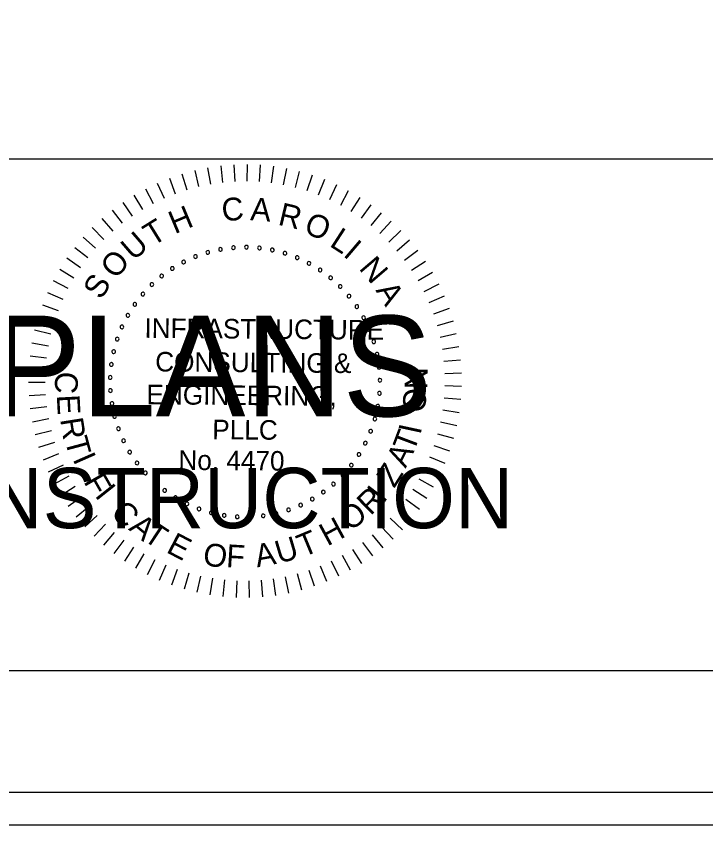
# Model space of a CAD drawing. Extents: x 967 to 1326, y 964 to 2584.
# Drawn here: x 1189.3 to 1212.88, y 2363.72 to 2391.36 of the extents above; entities that cross this region are included whole.
import ezdxf

# ---------------------------------------------------------------- set-up
doc = ezdxf.new("R2010")
doc.units = 0
for name, color, linetype in [('RD_SHT_Misc1', 7, 'Continuous'), ('RD_SHT_Misc2', 7, 'Continuous'), ('RD_XS_ExPaveRet', 7, 'Continuous'), ('RD_XS_TX_Elev_EX', 7, 'Continuous')]:
    doc.layers.add(name, color=color, linetype=linetype)

msp = doc.modelspace()

# ---------------------------------------------------------------- linework, layer by layer
at = {"layer": 'RD_SHT_Misc1'}
for p, q in [((1195.846, 2386.181), (1195.945, 2385.62)), ((1196.292, 2386.245), (1196.357, 2385.68)), ((1196.742, 2386.282), (1196.772, 2385.714)), ((1197.194, 2386.292), (1197.189, 2385.723)), ((1197.645, 2386.274), (1197.606, 2385.706)), ((1198.094, 2386.228), (1198.02, 2385.664)), ((1198.54, 2386.156), (1198.432, 2385.596)), ((1194.968, 2385.971), (1195.134, 2385.427)), ((1195.403, 2386.09), (1195.536, 2385.536)), ((1198.98, 2386.056), (1198.838, 2385.504)), ((1199.414, 2385.929), (1199.238, 2385.387)), ((1194.122, 2385.656), (1194.353, 2385.136)), ((1194.54, 2385.827), (1194.739, 2385.293)), ((1199.839, 2385.777), (1199.63, 2385.246)), ((1200.253, 2385.598), (1200.013, 2385.082)), ((1193.715, 2385.461), (1193.978, 2384.956)), ((1200.656, 2385.395), (1200.385, 2384.894)), ((1193.321, 2385.241), (1193.614, 2384.752)), ((1201.047, 2385.167), (1200.745, 2384.684)), ((1192.94, 2384.997), (1193.263, 2384.528)), ((1201.422, 2384.917), (1201.092, 2384.453)), ((1192.576, 2384.731), (1192.926, 2384.282)), ((1201.781, 2384.643), (1201.424, 2384.2)), ((1192.228, 2384.443), (1192.605, 2384.016)), ((1202.124, 2384.349), (1201.739, 2383.928)), ((1191.899, 2384.134), (1192.301, 2383.731)), ((1202.447, 2384.034), (1202.038, 2383.638)), ((1191.589, 2383.805), (1192.015, 2383.428)), ((1202.751, 2383.7), (1202.318, 2383.329)), ((1191.299, 2383.459), (1191.748, 2383.108)), ((1203.034, 2383.348), (1202.579, 2383.004)), ((1191.032, 2383.095), (1191.501, 2382.772)), ((1203.294, 2382.979), (1202.82, 2382.664)), ((1190.787, 2382.716), (1191.274, 2382.422)), ((1203.532, 2382.595), (1203.04, 2382.31)), ((1190.565, 2382.323), (1191.07, 2382.059)), ((1203.746, 2382.198), (1203.237, 2381.943)), ((1190.368, 2381.916), (1190.888, 2381.684)), ((1203.936, 2381.788), (1203.412, 2381.564)), ((1190.196, 2381.499), (1190.729, 2381.299)), ((1204.1, 2381.367), (1203.563, 2381.176)), ((1190.05, 2381.072), (1190.594, 2380.905)), ((1204.238, 2380.937), (1203.691, 2380.779)), ((1189.93, 2380.636), (1190.484, 2380.503)), ((1204.349, 2380.5), (1203.794, 2380.375)), ((1189.837, 2380.195), (1190.398, 2380.095)), ((1204.434, 2380.056), (1203.872, 2379.966)), ((1189.771, 2379.748), (1190.337, 2379.683)), ((1204.491, 2379.608), (1203.925, 2379.552)), ((1189.732, 2379.298), (1190.301, 2379.267)), ((1204.522, 2379.158), (1203.953, 2379.137)), ((1189.721, 2378.847), (1190.29, 2378.851)), ((1204.524, 2378.706), (1203.955, 2378.72)), ((1189.737, 2378.396), (1190.306, 2378.434)), ((1204.499, 2378.256), (1203.932, 2378.304)), ((1189.781, 2377.946), (1190.346, 2378.019)), ((1204.447, 2377.807), (1203.884, 2377.89)), ((1189.852, 2377.5), (1190.412, 2377.608)), ((1204.367, 2377.363), (1203.81, 2377.479)), ((1189.951, 2377.06), (1190.502, 2377.201)), ((1204.261, 2376.924), (1203.712, 2377.074)), ((1190.076, 2376.626), (1190.617, 2376.8)), ((1204.128, 2376.492), (1203.589, 2376.676)), ((1190.227, 2376.2), (1190.757, 2376.408)), ((1203.969, 2376.07), (1203.442, 2376.286)), ((1190.403, 2375.785), (1190.92, 2376.024)), ((1190.605, 2375.381), (1191.106, 2375.651)), ((1203.784, 2375.658), (1203.271, 2375.906)), ((1203.574, 2375.258), (1203.078, 2375.537)), ((1190.831, 2374.99), (1191.315, 2375.291)), ((1203.341, 2374.871), (1202.862, 2375.18)), ((1191.081, 2374.614), (1191.545, 2374.943)), ((1203.085, 2374.5), (1202.626, 2374.837)), ((1191.353, 2374.253), (1191.796, 2374.61)), ((1191.646, 2373.91), (1192.067, 2374.293)), ((1202.806, 2374.145), (1202.368, 2374.509)), ((1191.96, 2373.585), (1192.356, 2373.994)), ((1202.506, 2373.807), (1202.092, 2374.197)), ((1192.293, 2373.28), (1192.664, 2373.712)), ((1202.186, 2373.488), (1201.796, 2373.903)), ((1192.644, 2372.996), (1192.988, 2373.45)), ((1201.847, 2373.19), (1201.484, 2373.628)), ((1193.011, 2372.734), (1193.327, 2373.208)), ((1201.491, 2372.912), (1201.155, 2373.372)), ((1193.394, 2372.495), (1193.68, 2372.987)), ((1200.731, 2372.425), (1200.453, 2372.922)), ((1201.119, 2372.657), (1200.811, 2373.136)), ((1193.791, 2372.279), (1194.047, 2372.788)), ((1194.2, 2372.088), (1194.424, 2372.612)), ((1200.331, 2372.217), (1200.083, 2372.73)), ((1194.62, 2371.923), (1194.812, 2372.459)), ((1195.05, 2371.783), (1195.208, 2372.33)), ((1199.495, 2371.877), (1199.312, 2372.416)), ((1199.918, 2372.034), (1199.702, 2372.561)), ((1195.487, 2371.67), (1195.612, 2372.225)), ((1195.93, 2371.584), (1196.021, 2372.146)), ((1196.377, 2371.524), (1196.434, 2372.091)), ((1196.828, 2371.493), (1196.85, 2372.062)), ((1197.279, 2371.488), (1197.267, 2372.058)), ((1197.73, 2371.512), (1197.683, 2372.079)), ((1198.179, 2371.562), (1198.097, 2372.126)), ((1198.624, 2371.64), (1198.508, 2372.198)), ((1199.063, 2371.745), (1198.913, 2372.295))]:
    msp.add_line(p, q, dxfattribs=at)
for centre, start, end in [((1196.285, 2383.388), 10.6038, 190.6038), ((1196.285, 2383.388), 190.6038, 10.6038), ((1196.727, 2383.447), 5.0653, 185.0653), ((1196.727, 2383.447), 185.0653, 5.0653), ((1197.172, 2383.464), 359.5268, 179.5268), ((1197.172, 2383.464), 179.5268, 359.5268), ((1197.617, 2383.438), 173.9884, 353.9884), ((1197.617, 2383.438), 353.9884, 173.9884), ((1198.057, 2383.369), 168.4499, 348.4499), ((1198.057, 2383.369), 348.4499, 168.4499), ((1195.429, 2383.142), 21.6807, 201.6807), ((1195.429, 2383.142), 201.6807, 21.6807), ((1195.851, 2383.285), 16.1422, 196.1422), ((1195.851, 2383.285), 196.1422, 16.1422), ((1198.489, 2383.258), 162.9114, 342.9114), ((1198.489, 2383.258), 342.9114, 162.9114), ((1198.908, 2383.106), 157.373, 337.373), ((1198.908, 2383.106), 337.373, 157.373), ((1195.023, 2382.958), 27.2191, 207.2191), ((1195.023, 2382.958), 207.2191, 27.2191), ((1199.31, 2382.914), 151.8345, 331.8345), ((1199.31, 2382.914), 331.8345, 151.8345), ((1194.637, 2382.736), 32.7576, 212.7576), ((1194.637, 2382.736), 212.7576, 32.7576), ((1199.692, 2382.684), 146.2961, 326.2961), ((1199.692, 2382.684), 326.2961, 146.2961), ((1194.274, 2382.478), 38.2961, 218.2961), ((1194.274, 2382.478), 218.2961, 38.2961), ((1200.05, 2382.419), 140.7576, 320.7576), ((1200.05, 2382.419), 320.7576, 140.7576), ((1193.937, 2382.186), 43.8345, 223.8345), ((1193.937, 2382.186), 223.8345, 43.8345), ((1200.38, 2382.12), 135.2191, 315.2191), ((1200.38, 2382.12), 315.2191, 135.2191), ((1193.63, 2381.862), 49.373, 229.373), ((1193.63, 2381.862), 229.373, 49.373), ((1200.68, 2381.79), 129.6807, 309.6807), ((1200.68, 2381.79), 309.6807, 129.6807), ((1193.356, 2381.511), 54.9114, 234.9114), ((1193.356, 2381.511), 234.9114, 54.9114), ((1200.947, 2381.433), 124.1422, 304.1422), ((1200.947, 2381.433), 304.1422, 124.1422), ((1193.117, 2381.135), 60.4499, 240.4499), ((1193.117, 2381.135), 240.4499, 60.4499), ((1201.179, 2381.052), 118.6038, 298.6038), ((1201.179, 2381.052), 298.6038, 118.6038), ((1192.915, 2380.737), 65.9884, 245.9884), ((1192.915, 2380.737), 245.9884, 65.9884), ((1201.372, 2380.651), 113.0653, 293.0653), ((1201.372, 2380.651), 293.0653, 113.0653), ((1192.753, 2380.322), 71.5268, 251.5268), ((1192.753, 2380.322), 251.5268, 71.5268), ((1201.526, 2380.233), 107.5268, 287.5268), ((1201.526, 2380.233), 287.5268, 107.5268), ((1192.632, 2379.894), 77.0653, 257.0653), ((1192.632, 2379.894), 257.0653, 77.0653), ((1201.638, 2379.801), 101.9884, 281.9884), ((1201.638, 2379.801), 281.9884, 101.9884), ((1192.552, 2379.455), 82.6038, 262.6038), ((1192.552, 2379.455), 262.6038, 82.6038), ((1201.709, 2379.361), 96.4499, 276.4499), ((1201.709, 2379.361), 276.4499, 96.4499), ((1192.515, 2379.011), 88.1422, 268.1422), ((1192.515, 2379.011), 268.1422, 88.1422), ((1201.737, 2378.917), 90.9114, 270.9114), ((1201.737, 2378.917), 270.9114, 90.9114), ((1192.522, 2378.565), 93.6807, 273.6807), ((1192.522, 2378.565), 273.6807, 93.6807), ((1201.721, 2378.471), 85.373, 265.373), ((1201.721, 2378.471), 265.373, 85.373), ((1192.571, 2378.122), 99.2191, 279.2191), ((1192.571, 2378.122), 279.2191, 99.2191), ((1201.663, 2378.029), 79.8345, 259.8345), ((1201.663, 2378.029), 259.8345, 79.8345), ((1192.662, 2377.686), 104.7576, 284.7576), ((1192.662, 2377.686), 284.7576, 104.7576), ((1201.563, 2377.595), 74.2961, 254.2961), ((1201.563, 2377.595), 254.2961, 74.2961), ((1192.796, 2377.261), 110.2961, 290.2961), ((1192.796, 2377.261), 290.2961, 110.2961), ((1201.42, 2377.173), 68.7576, 248.7576), ((1201.42, 2377.173), 248.7576, 68.7576), ((1192.97, 2376.851), 115.8345, 295.8345), ((1192.97, 2376.851), 295.8345, 115.8345), ((1201.238, 2376.766), 63.2191, 243.2191), ((1201.238, 2376.766), 243.2191, 63.2191), ((1193.182, 2376.459), 121.373, 301.373), ((1193.182, 2376.459), 301.373, 121.373), ((1201.018, 2376.379), 57.6807, 237.6807), ((1201.018, 2376.379), 237.6807, 57.6807), ((1193.432, 2376.09), 126.9114, 306.9114), ((1193.432, 2376.09), 306.9114, 126.9114), ((1200.761, 2376.014), 52.1422, 232.1422), ((1200.761, 2376.014), 232.1422, 52.1422), ((1193.715, 2375.746), 132.4499, 312.4499), ((1193.715, 2375.746), 312.4499, 132.4499), ((1200.47, 2375.677), 46.6038, 226.6038), ((1200.47, 2375.677), 226.6038, 46.6038), ((1194.031, 2375.431), 137.9884, 317.9884), ((1194.031, 2375.431), 317.9884, 137.9884), ((1200.148, 2375.369), 41.0653, 221.0653), ((1200.148, 2375.369), 221.0653, 41.0653), ((1194.376, 2375.149), 143.5268, 323.5268), ((1194.376, 2375.149), 323.5268, 143.5268), ((1199.798, 2375.093), 35.5268, 215.5268), ((1199.798, 2375.093), 215.5268, 35.5268), ((1194.746, 2374.901), 149.0653, 329.0653), ((1194.746, 2374.901), 329.0653, 149.0653), ((1199.422, 2374.853), 29.9884, 209.9884), ((1199.422, 2374.853), 209.9884, 29.9884), ((1195.139, 2374.69), 154.6038, 334.6038), ((1195.139, 2374.69), 334.6038, 154.6038), ((1195.55, 2374.517), 160.1422, 340.1422), ((1195.55, 2374.517), 340.1422, 160.1422), ((1198.611, 2374.486), 18.9114, 198.9114), ((1199.026, 2374.65), 24.4499, 204.4499), ((1199.026, 2374.65), 204.4499, 24.4499), ((1195.975, 2374.386), 165.6807, 345.6807), ((1195.975, 2374.386), 345.6807, 165.6807), ((1196.412, 2374.295), 171.2191, 351.2191), ((1196.412, 2374.295), 351.2191, 171.2191), ((1196.855, 2374.248), 356.7576, 176.7576), ((1197.301, 2374.243), 2.2961, 182.2961), ((1197.745, 2374.282), 7.8345, 187.8345), ((1197.745, 2374.282), 187.8345, 7.8345), ((1198.183, 2374.363), 13.373, 193.373), ((1198.183, 2374.363), 193.373, 13.373), ((1198.611, 2374.486), 198.9114, 18.9114), ((1196.855, 2374.248), 176.7576, 356.7576), ((1197.301, 2374.243), 182.2961, 2.2961)]:
    msp.add_arc(centre, 0.0627, start, end, dxfattribs=at)
at = {"layer": 'RD_XS_ExPaveRet'}
for points in [[(967.409, 2363.72), (1326.285, 2363.72), (1326.285, 2583.72), (967.409, 2583.72)], [(988.525, 2364.84), (1326.285, 2364.84), (1326.285, 2582.6), (988.525, 2582.6)]]:
    msp.add_lwpolyline(points, close=True, dxfattribs=at)
at = {"layer": 'RD_XS_TX_Elev_EX'}
for p, q in [((996.114, 2386.486), (1323.886, 2386.486)), ((1323.886, 2368.983), (996.114, 2368.983))]:
    msp.add_line(p, q, dxfattribs=at)

# ---------------------------------------------------------------- texts
at = {"layer": 'RD_SHT_Misc1'}
for s, height, rotation, p in [('C', 0.78, 4.7281, (1196.355, 2384.346)), ('A', 0.78, 355.6981, (1197.29, 2384.39)), ('H', 0.78, 22.7882, (1194.72, 2383.904)), ('R', 0.78, 346.6681, (1198.222, 2384.238)), ('O', 0.78, 337.638, (1199.096, 2383.972)), ('T', 0.78, 31.8182, (1193.961, 2383.478)), ('U', 0.78, 40.8482, (1193.306, 2382.976)), ('L', 0.78, 327.108, (1199.981, 2383.52)), ('I', 0.78, 319.578, (1200.451, 2383.182)), ('O', 0.78, 49.8782, (1192.707, 2382.341)), ('N', 0.78, 310.548, (1200.994, 2382.728)), ('S', 0.78, 58.9083, (1192.211, 2381.642)), ('A', 0.78, 301.5179, (1201.576, 2381.991)), ('INFRASTRUCTURE', 0.66873, 359.5268, (1193.682, 2380.367)), ('CONSULTING &', 0.66873, 359.5268, (1194.051, 2379.217)), ('N', 0.78, 89.2085, (1203.359, 2378.604)), ('C', 0.78, 267.025, (1190.646, 2379.227)), ('ENGINEERING,', 0.66873, 359.5268, (1193.751, 2378.095)), ('O', 0.78, 83.2085, (1203.26, 2377.786)), ('E', 0.78, 273.025, (1190.685, 2378.408)), ('R', 0.78, 279.025, (1190.799, 2377.583)), ('PLLC', 0.6687, 359.5268, (1196.002, 2376.9)), ('I', 0.78, 77.9093, (1203.121, 2377.032)), ('T', 0.78, 285.025, (1190.955, 2376.878)), ('T', 0.78, 69.3954, (1202.891, 2376.428)), ('No. 4470', 0.6687, 359.5268, (1194.843, 2375.855)), ('A', 0.78, 63.3954, (1202.616, 2375.888)), ('I', 0.78, 293.7713, (1191.221, 2376.225)), ('Z', 0.78, 57.3954, (1202.224, 2375.206)), ('F', 0.78, 299.7713, (1191.589, 2375.455)), ('I', 0.78, 308.5268, (1191.965, 2374.973)), ('R', 0.78, 44.5268, (1201.415, 2374.267)), ('I', 0.78, 52.3339, (1201.856, 2374.69)), ('C', 0.78, 314.5268, (1192.496, 2374.346)), ('O', 0.78, 38.5268, (1200.73, 2373.731)), ('A', 0.78, 320.5268, (1193.115, 2373.822)), ('T', 0.78, 326.5268, (1193.602, 2373.478)), ('H', 0.78, 28.5268, (1199.942, 2373.23)), ('E', 0.78, 332.5268, (1194.394, 2373.051)), ('T', 0.78, 22.5268, (1199.108, 2372.856)), ('U', 0.78, 16.5268, (1198.288, 2372.638)), ('O', 0.78, 350.5268, (1195.647, 2372.614)), ('F', 0.78, 356.5268, (1196.465, 2372.532)), ('A', 0.78, 10.5268, (1197.537, 2372.517))]:
    msp.add_text(s, height=height, rotation=rotation, dxfattribs=at).set_placement(p)
at = {"layer": 'RD_SHT_Misc2'}
for s, height, p in [('FINAL PLANS', 3.4375, (1174.145, 2377.685)), ('NOT FOR CONSTRUCTION', 2.0625, (1170.901, 2373.86))]:
    msp.add_text(s, height=height, dxfattribs=at).set_placement(p)

doc.saveas('drawing.dxf')
